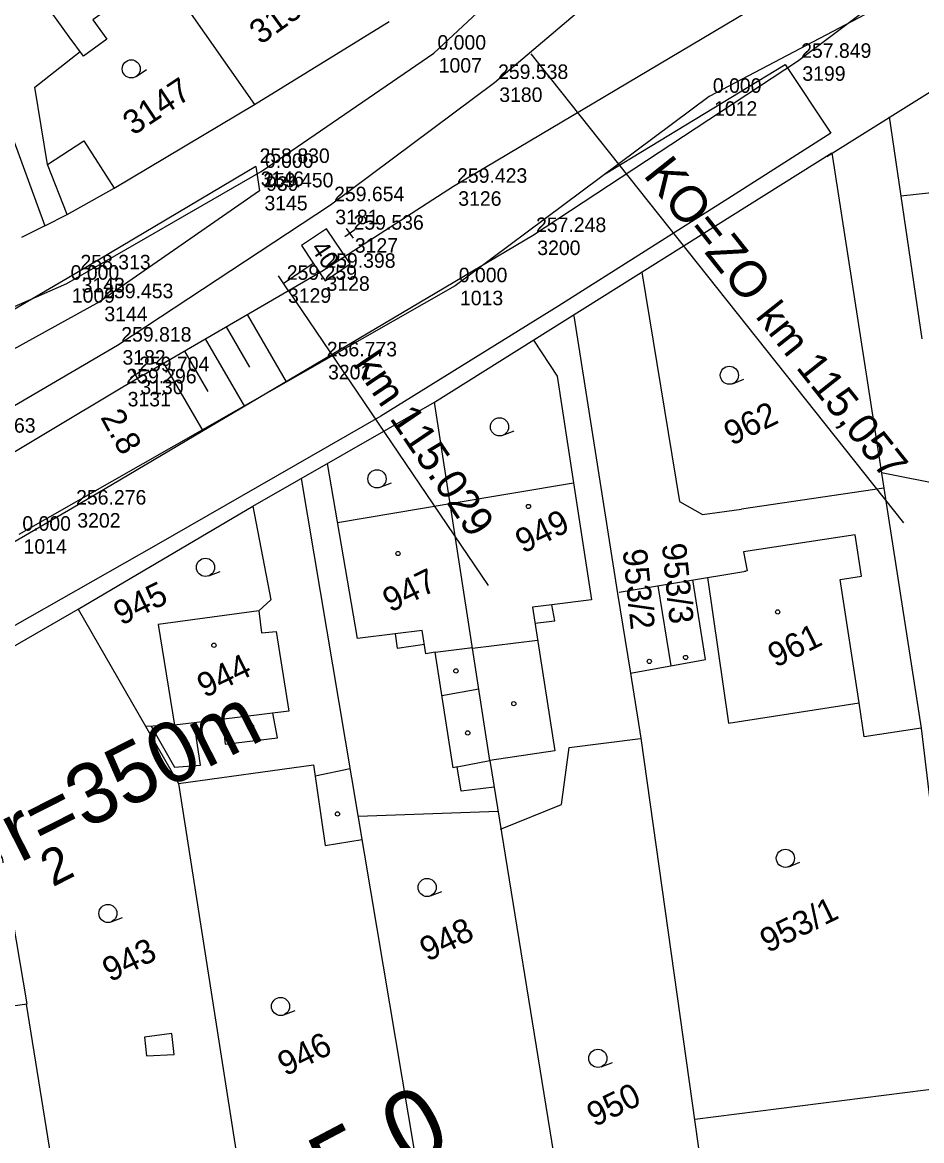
# Model space of a CAD drawing. Extents: x -496688 to -495455, y -1089309 to -1088026.
# Drawn here: x -495946.7 to -495872.4, y -1089215.3 to -1089122.9 of the extents above; entities that cross this region are included whole.
import ezdxf

# ---------------------------------------------------------------- set-up
doc = ezdxf.new("R2010")
doc.units = 0
for name, color, linetype in [('Vrstva 1', 7, 'Continuous'), ('Vrstva 23', 7, 'Continuous'), ('Vrstva 4', 7, 'Continuous'), ('Vrstva 48', 7, 'Continuous'), ('Vrstva 49', 7, 'Continuous'), ('Vrstva 5', 7, 'Continuous'), ('Vrstva 52', 7, 'Continuous'), ('Vrstva 53', 7, 'Continuous'), ('Vrstva 55', 7, 'Continuous'), ('Vrstva 56', 7, 'Continuous'), ('Vrstva 57', 7, 'Continuous'), ('Vrstva 58', 7, 'Continuous'), ('Vrstva 59', 7, 'Continuous'), ('Vrstva 60', 7, 'Continuous'), ('Vrstva 61', 7, 'Continuous'), ('Vrstva 7', 7, 'Continuous')]:
    doc.layers.add(name, color=color, linetype=linetype)

msp = doc.modelspace()

# ---------------------------------------------------------------- linework, layer by layer
at = {"layer": 'Vrstva 1'}
msp.add_line((-495904.651, -1089125.498), (-495873.866, -1089164.268), dxfattribs=at)
msp.add_lwpolyline([(-496014.19, -1089184.49), (-496002.71, -1089180.6), (-495995.088, -1089177.692), (-495975.672, -1089169.34), (-495956.891, -1089159.948), (-495951.688, -1089157.109), (-495938.804, -1089149.587), (-495921.214, -1089137.985), (-495907.663, -1089127.884), (-495890.17, -1089113.043)], dxfattribs=at)
at = {"layer": 'Vrstva 23'}
for p, q in [((-495942.82, -1089124.09), (-495945.78, -1089119.95)), ((-495941.62, -1089125.7), (-495942.82, -1089124.09)), ((-495875.038, -1089130.725), (-495872.327, -1089149.059)), ((-495904.445, -1089149.16), (-495902.478, -1089152.129)), ((-495902.478, -1089152.129), (-495901.129, -1089160.965)), ((-495908.031, -1089183.894), (-495912.606, -1089154.279)), ((-495877.328, -1089168.66), (-495877.851, -1089165.252)), ((-495887.089, -1089166.641), (-495886.772, -1089168.217)), ((-495897.354, -1089169.976), (-495886.884, -1089168.244)), ((-495886.772, -1089168.217), (-495886.997, -1089168.272)), ((-495890.213, -1089175.56), (-495891.262, -1089168.978)), ((-495890.063, -1089168.779), (-495888.323, -1089180.812)), ((-495879.083, -1089168.933), (-495877.328, -1089168.66)), ((-495877.523, -1089179.121), (-495879.083, -1089168.933)), ((-495897.478, -1089170.086), (-495896.424, -1089176.684)), ((-495894.15, -1089169.455), (-495893.095, -1089176.082)), ((-495904.528, -1089171.222), (-495902.672, -1089183.091)), ((-495927.131, -1089171.526), (-495935.467, -1089172.671)), ((-495927.131, -1089171.526), (-495926.902, -1089173.342)), ((-495935.467, -1089172.671), (-495934.117, -1089180.964)), ((-495926.902, -1089173.342), (-495925.7, -1089173.225)), ((-495915.866, -1089173.433), (-495918.99, -1089173.819)), ((-495915.866, -1089173.434), (-495915.696, -1089174.622)), ((-495913.328, -1089175.068), (-495913.643, -1089173.16)), ((-495915.696, -1089174.622), (-495913.445, -1089174.286)), ((-495912.55, -1089174.951), (-495913.328, -1089175.068)), ((-495911.085, -1089184.496), (-495912.55, -1089174.951)), ((-495896.424, -1089176.684), (-495890.213, -1089175.56)), ((-495888.323, -1089180.812), (-495877.523, -1089179.121)), ((-495932.488, -1089180.793), (-495934.117, -1089180.964)), ((-495902.672, -1089183.091), (-495908.031, -1089183.894)), ((-495908.031, -1089183.894), (-495901.815, -1089222.356)), ((-495922.62, -1089184.24), (-495921.655, -1089190.919)), ((-495910.744, -1089184.428), (-495911.085, -1089184.496)), ((-495910.425, -1089186.431), (-495910.744, -1089184.428)), ((-495907.677, -1089186.086), (-495910.425, -1089186.431)), ((-495921.655, -1089190.919), (-495918.595, -1089190.413))]:
    msp.add_line(p, q, dxfattribs=at)
for points in [[(-495935.23, -1089118.65), (-495940.86, -1089122.69), (-495939.71, -1089124.29), (-495941.62, -1089125.7)], [(-495904.322, -1089172.544), (-495902.67, -1089172.345), (-495902.921, -1089171.024)], [(-495930.142, -1089180.5), (-495929.92, -1089182.547), (-495925.605, -1089182.012), (-495925.969, -1089179.979)]]:
    msp.add_lwpolyline(points, dxfattribs=at)
at = {"layer": 'Vrstva 4'}
msp.add_line((-495942.98, -1089138.79), (-495939.09, -1089136.61), dxfattribs=at)
at = {"layer": 'Vrstva 48'}
for p, q in [((-495924.852, -1089152.599), (-495928.075, -1089147.052)), ((-495927.866, -1089151.393), (-495929.804, -1089148.056)), ((-495928.296, -1089154.635), (-495931.534, -1089149.061)), ((-495931.316, -1089153.418), (-495933.263, -1089150.066)), ((-495931.739, -1089156.67), (-495934.992, -1089151.07))]:
    msp.add_line(p, q, dxfattribs=at)
at = {"layer": 'Vrstva 49'}
for points in [[(-495858.07, -1089106.445), (-495869.622, -1089111.246), (-495885.061, -1089121.015), (-495911.05, -1089136.462), (-495921.935, -1089143.485), (-495938.378, -1089153.037), (-495956.605, -1089163.96), (-495973.859, -1089172.382), (-495993.672, -1089180.931), (-496000, -1089183.365)], [(-495858.07, -1089106.445), (-495866.186, -1089113.792), (-495882.612, -1089126.137), (-495904.522, -1089140.533), (-495921.815, -1089150.804), (-495942.535, -1089163.052), (-495957.623, -1089171.808)], [(-495927.376, -1089134.825), (-495927.07, -1089136.84), (-495940.299, -1089146), (-495959.349, -1089156.497), (-495976.525, -1089165.875), (-495996.329, -1089174.254), (-496000, -1089175.783)], [(-495927.376, -1089134.825), (-495942.178, -1089143.616), (-495956.416, -1089151.915), (-495976.548, -1089162.987)]]:
    msp.add_lwpolyline(points, dxfattribs=at)
at = {"layer": 'Vrstva 5'}
msp.add_line((-495925.542, -1089143.857), (-495924.708, -1089145.103), dxfattribs=at)
msp.add_lwpolyline([(-495925.125, -1089144.48), (-495922.633, -1089142.81), (-495921.658, -1089144.264), (-495919.582, -1089142.872), (-495921.531, -1089139.965), (-495923.606, -1089141.356), (-495922.633, -1089142.81)], dxfattribs=at)
at = {"layer": 'Vrstva 52'}
for p, q in [((-495869.066, -1089136.706), (-495874.071, -1089137.262)), ((-495918.99, -1089173.819), (-495921.456, -1089159.346)), ((-495911.31, -1089162.667), (-495901.129, -1089160.965)), ((-495901.128, -1089160.965), (-495899.653, -1089170.619)), ((-495920.625, -1089164.224), (-495911.31, -1089162.667)), ((-495877.851, -1089165.252), (-495887.089, -1089166.641)), ((-495902.921, -1089171.023), (-495904.528, -1089171.222)), ((-495899.653, -1089170.619), (-495902.921, -1089171.024)), ((-495925.7, -1089173.225), (-495924.642, -1089179.813)), ((-495913.643, -1089173.16), (-495915.866, -1089173.434)), ((-495909.465, -1089174.614), (-495904.1, -1089173.965)), ((-495912.55, -1089174.951), (-495909.475, -1089174.547)), ((-495912, -1089178.535), (-495908.946, -1089177.972)), ((-495924.642, -1089179.813), (-495932.488, -1089180.793)), ((-495910.744, -1089184.428), (-495908.031, -1089183.894)), ((-495922.489, -1089185.152), (-495919.579, -1089184.567))]:
    msp.add_line(p, q, dxfattribs=at)
at = {"layer": 'Vrstva 53'}
for p, q in [((-495848.7, -1089107.35), (-495889.91, -1089129.03)), ((-495910.91, -1089144.68), (-495946.98, -1089165.21)), ((-495910.91, -1089144.68), (-495946.98, -1089165.21))]:
    msp.add_line(p, q, dxfattribs=at)
msp.add_lwpolyline([(-496003.69, -1089162.25), (-495953.55, -1089149.11), (-495942.99, -1089144.47), (-495926.93, -1089135.23), (-495912.67, -1089125.46), (-495889.86, -1089104.18), (-495891.19, -1089098.87), (-495883.3, -1089091.04), (-495885.09, -1089084.82), (-495889.2, -1089069.28), (-495896.83, -1089074.5), (-495903.1, -1089077.44), (-495922.4, -1089086.52), (-495936.17, -1089093), (-495941.97, -1089094.48), (-495950.57, -1089096.68), (-495959.93, -1089099.22), (-495969.43, -1089101.74), (-495984.52, -1089104.87), (-495998.23, -1089105.95), (-496014.76, -1089107.64)], dxfattribs=at)
at = {"layer": 'Vrstva 55'}
for p, q in [((-495848.7, -1089107.35), (-495889.91, -1089129.03)), ((-495935.23, -1089118.65), (-495927.49, -1089129.69)), ((-495927.49, -1089129.69), (-495916.37, -1089122.85)), ((-495949.95, -1089125.72), (-495944.82, -1089139.71)), ((-495945.66, -1089128.27), (-495941.913, -1089125.307)), ((-495944.59, -1089134.64), (-495945.66, -1089128.27)), ((-495939.09, -1089136.61), (-495927.49, -1089129.69)), ((-495889.91, -1089129.03), (-495910.91, -1089144.68)), ((-495889.91, -1089129.03), (-495910.91, -1089144.68)), ((-495944.59, -1089134.64), (-495941.6, -1089132.69)), ((-495941.6, -1089132.69), (-495939.09, -1089136.61)), ((-495942.98, -1089138.79), (-495944.59, -1089134.64)), ((-495888.069, -1089137.285), (-495902.353, -1089146.325)), ((-495944.82, -1089139.71), (-495942.98, -1089138.79)), ((-495944.82, -1089139.71), (-495946.74, -1089140.67)), ((-495902.353, -1089146.325), (-495917.041, -1089155.438)), ((-495901.113, -1089147.145), (-495897.478, -1089170.086)), ((-495852.255, -1089164.807), (-495875.677, -1089160.121)), ((-495875.478, -1089161.4), (-495872.382, -1089181.216)), ((-495927.619, -1089162.875), (-495926.134, -1089170.617)), ((-495935.622, -1089166.091), (-495956.247, -1089177.785)), ((-495926.134, -1089170.617), (-495927.131, -1089171.526)), ((-495896.424, -1089176.684), (-495895.565, -1089182.057)), ((-495877.093, -1089181.929), (-495877.523, -1089179.121)), ((-495934.117, -1089180.964), (-495936.485, -1089181.096)), ((-495936.031, -1089181.071), (-495934.113, -1089184.436)), ((-495931.943, -1089184.289), (-495932.488, -1089180.793)), ((-495872.382, -1089181.216), (-495877.093, -1089181.929)), ((-495933.783, -1089185.785), (-495922.62, -1089184.24)), ((-495918.92, -1089188.485), (-495907.354, -1089188.088)), ((-495946.352, -1089204.038), (-495931.864, -1089294.803)), ((-495934.314, -1089206.457), (-495936.588, -1089206.742)), ((-495936.588, -1089206.742), (-495936.414, -1089208.288)), ((-495934.126, -1089208.193), (-495934.314, -1089206.457)), ((-495868.6, -1089210.69), (-495891.112, -1089213.558))]:
    msp.add_line(p, q, dxfattribs=at)
for points in [[(-495880.192, -1089133.982), (-495869.793, -1089127.495), (-495859.943, -1089121.2), (-495839.101, -1089108.469)], [(-495898.506, -1089135.436), (-495883.638, -1089126.381), (-495879.853, -1089132.059), (-495888.069, -1089137.285)], [(-495887.988, -1089138.838), (-495879.788, -1089133.688), (-495875.478, -1089161.4), (-495887.241, -1089163.138)], [(-495988.097, -1089197.76), (-495955.888, -1089179.36), (-495942.075, -1089171.397), (-495927.619, -1089162.875), (-495912.606, -1089154.279), (-495887.988, -1089138.838)], [(-495895.479, -1089143.537), (-495892.363, -1089162.5), (-495890.475, -1089163.579), (-495887.241, -1089163.138)], [(-495942.075, -1089171.397), (-495933.783, -1089185.785), (-495928.189, -1089221.504), (-495913.717, -1089219.4), (-495923.615, -1089160.583)], [(-495986.221, -1089209.442), (-495946.285, -1089203.998), (-495948.307, -1089191.951), (-495955.821, -1089179.32)], [(-495872.382, -1089181.216), (-495870.106, -1089200.304), (-495847.808, -1089196.133)], [(-495907.156, -1089189.578), (-495902.127, -1089187.522), (-495901.477, -1089182.82), (-495895.582, -1089182.066)], [(-495895.565, -1089182.057), (-495890.581, -1089217.506), (-495886.031, -1089246.24)]]:
    msp.add_lwpolyline(points, dxfattribs=at)
at = {"layer": 'Vrstva 56'}
for p, q in [((-495942.98, -1089138.79), (-495939.09, -1089136.61)), ((-495917.041, -1089155.438), (-495935.622, -1089166.091)), ((-495934.113, -1089184.436), (-495931.943, -1089184.289)), ((-495936.414, -1089208.288), (-495934.126, -1089208.193))]:
    msp.add_line(p, q, dxfattribs=at)
at = {"layer": 'Vrstva 58'}
for p, q in [((-495937.26, -1089127.375), (-495936.432, -1089126.815)), ((-495887.973, -1089152.763), (-495887.042, -1089152.399)), ((-495906.97, -1089157.027), (-495906.039, -1089156.663)), ((-495917.094, -1089161.323), (-495916.163, -1089160.959)), ((-495931.272, -1089168.634), (-495930.341, -1089168.27)), ((-495883.343, -1089192.671), (-495882.412, -1089192.307)), ((-495912.953, -1089195.083), (-495912.022, -1089194.719)), ((-495939.337, -1089197.231), (-495938.406, -1089196.867)), ((-495925.068, -1089204.914), (-495924.137, -1089204.55)), ((-495898.84, -1089209.201), (-495897.909, -1089208.837))]:
    msp.add_line(p, q, dxfattribs=at)
for centre in [(-495937.679, -1089126.752), (-495888.244, -1089152.064), (-495907.242, -1089156.328), (-495917.366, -1089160.624), (-495931.544, -1089167.934), (-495883.614, -1089191.972), (-495913.225, -1089194.384), (-495939.609, -1089196.532), (-495925.34, -1089204.216), (-495899.112, -1089208.502)]:
    msp.add_circle(centre, 0.75, dxfattribs=at)
at = {"layer": 'Vrstva 59'}
for centre in [(-495904.856, -1089162.908), (-495915.631, -1089166.793), (-495884.253, -1089171.617), (-495930.849, -1089174.374), (-495894.863, -1089175.711), (-495891.866, -1089175.382), (-495910.848, -1089176.493), (-495906.063, -1089179.196), (-495927.749, -1089181.064), (-495909.866, -1089181.618), (-495920.633, -1089188.308)]:
    msp.add_circle(centre, 0.175, dxfattribs=at)
at = {"layer": 'Vrstva 60'}
for p, q in [((-495912.67, -1089125.46), (-495912.67, -1089125.46)), ((-495912.67, -1089125.46), (-495912.67, -1089125.46)), ((-495882.612, -1089126.137), (-495882.612, -1089126.137)), ((-495882.612, -1089126.137), (-495882.612, -1089126.137)), ((-495907.663, -1089127.884), (-495907.663, -1089127.884)), ((-495907.663, -1089127.884), (-495907.663, -1089127.884)), ((-495889.91, -1089129.03), (-495889.91, -1089129.03)), ((-495889.91, -1089129.03), (-495889.91, -1089129.03)), ((-495927.376, -1089134.825), (-495927.376, -1089134.825)), ((-495927.376, -1089134.825), (-495927.376, -1089134.825)), ((-495926.93, -1089135.23), (-495926.93, -1089135.23)), ((-495926.93, -1089135.23), (-495926.93, -1089135.23)), ((-495927.07, -1089136.84), (-495927.07, -1089136.84)), ((-495927.07, -1089136.84), (-495927.07, -1089136.84)), ((-495911.05, -1089136.462), (-495911.05, -1089136.462)), ((-495911.05, -1089136.462), (-495911.05, -1089136.462)), ((-495921.214, -1089137.985), (-495921.214, -1089137.985)), ((-495921.214, -1089137.985), (-495921.214, -1089137.985)), ((-495919.603, -1089140.337), (-495919.603, -1089140.337)), ((-495919.603, -1089140.337), (-495919.603, -1089140.337)), ((-495904.522, -1089140.533), (-495904.522, -1089140.533)), ((-495904.522, -1089140.533), (-495904.522, -1089140.533)), ((-495921.935, -1089143.485), (-495921.935, -1089143.485)), ((-495921.935, -1089143.485), (-495921.935, -1089143.485)), ((-495942.99, -1089144.47), (-495942.99, -1089144.47)), ((-495942.99, -1089144.47), (-495942.99, -1089144.47)), ((-495942.178, -1089143.616), (-495942.178, -1089143.616)), ((-495942.178, -1089143.616), (-495942.178, -1089143.616)), ((-495925.125, -1089144.48), (-495925.125, -1089144.48)), ((-495925.125, -1089144.48), (-495925.125, -1089144.48)), ((-495910.91, -1089144.68), (-495910.91, -1089144.68)), ((-495910.91, -1089144.68), (-495910.91, -1089144.68)), ((-495940.299, -1089146), (-495940.299, -1089146)), ((-495940.299, -1089146), (-495940.299, -1089146)), ((-495938.804, -1089149.587), (-495938.804, -1089149.587)), ((-495938.804, -1089149.587), (-495938.804, -1089149.587)), ((-495921.815, -1089150.804), (-495921.815, -1089150.804)), ((-495921.815, -1089150.804), (-495921.815, -1089150.804)), ((-495937.327, -1089152.028), (-495937.327, -1089152.028)), ((-495937.327, -1089152.028), (-495937.327, -1089152.028)), ((-495938.378, -1089153.037), (-495938.378, -1089153.037)), ((-495938.378, -1089153.037), (-495938.378, -1089153.037)), ((-495942.535, -1089163.052), (-495942.535, -1089163.052)), ((-495942.535, -1089163.052), (-495942.535, -1089163.052))]:
    msp.add_line(p, q, dxfattribs=at)
at = {"layer": 'Vrstva 7'}
for p, q in [((-495919.193, -1089140.051), (-495920.013, -1089140.623)), ((-495919.317, -1089140.747), (-495919.889, -1089139.927)), ((-495924.674, -1089145.076), (-495908.172, -1089169.442)), ((-495936.9, -1089151.768), (-495937.754, -1089152.288)), ((-495937.067, -1089152.455), (-495937.587, -1089151.601))]:
    msp.add_line(p, q, dxfattribs=at)

# ---------------------------------------------------------------- texts
at = {"layer": 'Vrstva 1'}
for s, height, rotation, p in [('KO=ZO', 3, 308.45082, (-495895.427, -1089135.53)), ('km 115,057', 2.5, 308.45082, (-495886.147, -1089147.222)), ('r=350m', 5, 26.85953, (-495946.919, -1089192.391)), ('2', 3, 27.02082, (-495944.175, -1089194.377))]:
    msp.add_text(s, height=height, rotation=rotation, dxfattribs=at).set_placement(p)
at = {"layer": 'Vrstva 48'}
msp.add_text('2.8', height=2, rotation=298.61983, dxfattribs=at).set_placement((-495940.259, -1089155.532))
at = {"layer": 'Vrstva 5'}
msp.add_text('40', height=1.5, rotation=303.82593, dxfattribs=at).set_placement((-495922.888, -1089141.58))
at = {"layer": 'Vrstva 57'}
for s, rotation, p in [('3151', 35.66778, (-495926.991, -1089124.805)), ('3147', 33.54414, (-495937.515, -1089132.302)), ('962', 26.09057, (-495888.063, -1089157.915)), ('949', 26.09057, (-495905.301, -1089166.82)), ('953/2', 275.94789, (-495897.067, -1089166.504)), ('953/3', 275.71059, (-495893.827, -1089166.025)), ('947', 26.09057, (-495916.267, -1089171.696)), ('945', 26.09057, (-495938.51, -1089172.771)), ('961', 26.09057, (-495884.433, -1089176.253)), ('944', 26.09057, (-495931.607, -1089178.755)), ('953/1', 26.09057, (-495885.084, -1089199.824)), ('948', 26.09057, (-495913.2, -1089200.545)), ('943', 26.09057, (-495939.43, -1089202.233)), ('946', 26.09057, (-495924.947, -1089210.009)), ('950', 26.09057, (-495899.394, -1089214.203))]:
    msp.add_text(s, height=2, rotation=rotation, dxfattribs=at).set_placement(p)
at = {"layer": 'Vrstva 60'}
for s, p in [('1007', (-495912.27, -1089127.06)), ('1007', (-495912.27, -1089127.06)), ('3199', (-495882.212, -1089127.737)), ('3199', (-495882.212, -1089127.737)), ('3180', (-495907.263, -1089129.484)), ('3180', (-495907.263, -1089129.484)), ('1012', (-495889.51, -1089130.63)), ('1012', (-495889.51, -1089130.63)), ('3146', (-495926.976, -1089136.425)), ('3146', (-495926.976, -1089136.425)), ('939', (-495926.53, -1089136.83)), ('939', (-495926.53, -1089136.83)), ('3126', (-495910.65, -1089138.062)), ('3126', (-495910.65, -1089138.062)), ('3145', (-495926.67, -1089138.44)), ('3145', (-495926.67, -1089138.44)), ('3181', (-495920.814, -1089139.585)), ('3181', (-495920.814, -1089139.585)), ('3127', (-495919.203, -1089141.937)), ('3127', (-495919.203, -1089141.937)), ('3200', (-495904.122, -1089142.133)), ('3200', (-495904.122, -1089142.133)), ('3143', (-495941.778, -1089145.216)), ('3143', (-495941.778, -1089145.216)), ('3128', (-495921.535, -1089145.085)), ('3128', (-495921.535, -1089145.085)), ('1009', (-495942.59, -1089146.07)), ('1009', (-495942.59, -1089146.07)), ('3129', (-495924.725, -1089146.08)), ('3129', (-495924.725, -1089146.08)), ('1013', (-495910.51, -1089146.28)), ('1013', (-495910.51, -1089146.28)), ('3144', (-495939.899, -1089147.6)), ('3144', (-495939.899, -1089147.6)), ('3182', (-495938.404, -1089151.187)), ('3182', (-495938.404, -1089151.187)), ('3201', (-495921.415, -1089152.404)), ('3201', (-495921.415, -1089152.404)), ('3130', (-495936.927, -1089153.628)), ('3130', (-495936.927, -1089153.628)), ('3131', (-495937.978, -1089154.637)), ('3131', (-495937.978, -1089154.637)), ('3202', (-495942.135, -1089164.652)), ('3202', (-495942.135, -1089164.652)), ('1014', (-495946.58, -1089166.81)), ('1014', (-495946.58, -1089166.81))]:
    msp.add_text(s, height=1.2, dxfattribs=at).set_placement(p)
at = {"layer": 'Vrstva 61'}
for s, p in [('0.000', (-495912.37, -1089125.16)), ('0.000', (-495912.37, -1089125.16)), ('257.849', (-495882.312, -1089125.837)), ('257.849', (-495882.312, -1089125.837)), ('259.538', (-495907.363, -1089127.584)), ('259.538', (-495907.363, -1089127.584)), ('0.000', (-495889.61, -1089128.73)), ('0.000', (-495889.61, -1089128.73)), ('258.830', (-495927.076, -1089134.525)), ('258.830', (-495927.076, -1089134.525)), ('0.000', (-495926.63, -1089134.93)), ('0.000', (-495926.63, -1089134.93)), ('259.423', (-495910.75, -1089136.162)), ('259.423', (-495910.75, -1089136.162)), ('259.450', (-495926.77, -1089136.54)), ('259.450', (-495926.77, -1089136.54)), ('259.654', (-495920.914, -1089137.685)), ('259.654', (-495920.914, -1089137.685)), ('259.536', (-495919.303, -1089140.037)), ('259.536', (-495919.303, -1089140.037)), ('257.248', (-495904.222, -1089140.233)), ('257.248', (-495904.222, -1089140.233)), ('258.313', (-495941.878, -1089143.316)), ('258.313', (-495941.878, -1089143.316)), ('259.398', (-495921.635, -1089143.185)), ('259.398', (-495921.635, -1089143.185)), ('0.000', (-495942.69, -1089144.17)), ('0.000', (-495942.69, -1089144.17)), ('259.259', (-495924.825, -1089144.18)), ('259.259', (-495924.825, -1089144.18)), ('0.000', (-495910.61, -1089144.38)), ('0.000', (-495910.61, -1089144.38)), ('259.453', (-495939.999, -1089145.7)), ('259.453', (-495939.999, -1089145.7)), ('259.818', (-495938.504, -1089149.287)), ('259.818', (-495938.504, -1089149.287)), ('256.773', (-495921.515, -1089150.504)), ('256.773', (-495921.515, -1089150.504)), ('259.704', (-495937.027, -1089151.728)), ('259.704', (-495937.027, -1089151.728)), ('259.296', (-495938.078, -1089152.737)), ('259.296', (-495938.078, -1089152.737)), ('259.963', (-495951.388, -1089156.809)), ('259.963', (-495951.388, -1089156.809)), ('256.276', (-495942.235, -1089162.752)), ('256.276', (-495942.235, -1089162.752)), ('0.000', (-495946.68, -1089164.91)), ('0.000', (-495946.68, -1089164.91))]:
    msp.add_text(s, height=1.2, dxfattribs=at).set_placement(p)
at = {"layer": 'Vrstva 7'}
for s, height, rotation, p in [('km 115.029', 2.5, 304.10843, (-495919.401, -1089151.164)), ('115.0', 6, 27.78226, (-495928.706, -1089225.088))]:
    msp.add_text(s, height=height, rotation=rotation, dxfattribs=at).set_placement(p)

doc.saveas('drawing.dxf')
